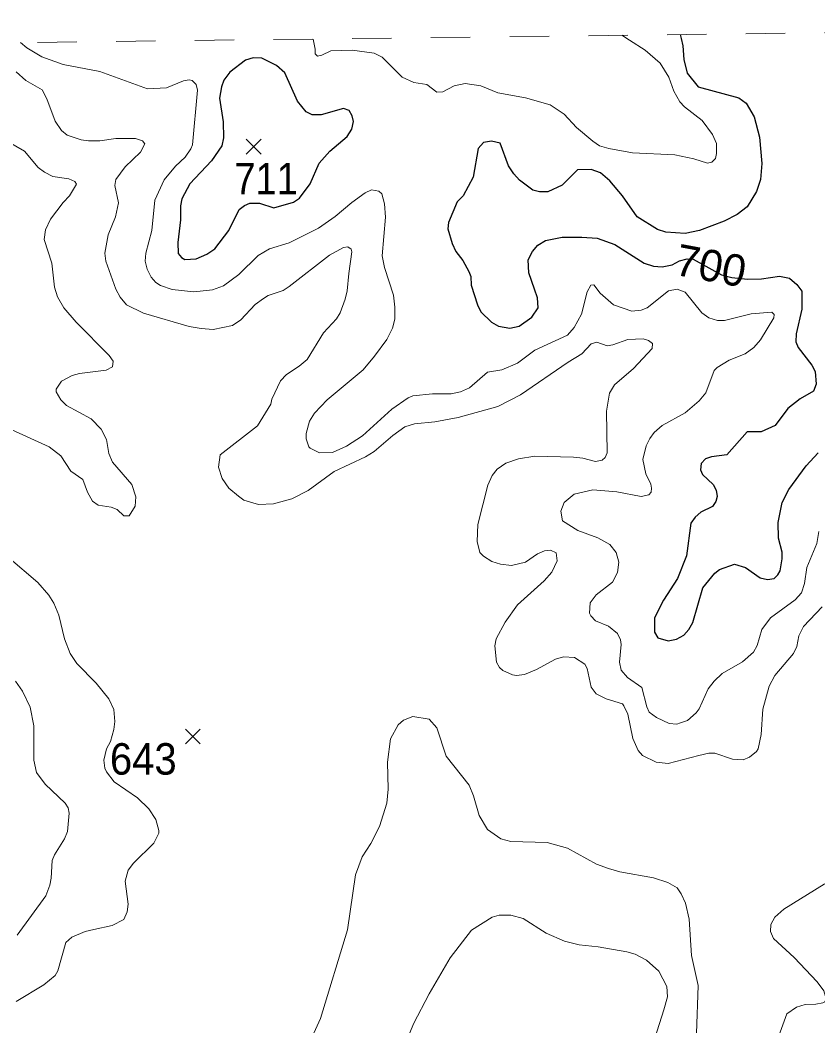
# Model space of a CAD drawing. Extents: x 294.2 to 320.3, y 7482.7 to 7510.7.
# Drawn here: x 315.257 to 317.284, y 7508.188 to 7510.744 of the extents above; entities that cross this region are included whole.
import ezdxf
from ezdxf.enums import TextEntityAlignment as Align

# ---------------------------------------------------------------- set-up
doc = ezdxf.new("R2010")
doc.units = 0
doc.header["$LTSCALE"] = 0.032
doc.linetypes.add('SHORT_DASHED', pattern=[2.7, 1.5, -1.2])
for name, color, linetype, lineweight in [('1', 7, 'Continuous', 25), ('2', 7, 'Continuous', 13), ('21', 7, 'Continuous', 25), ('22', 7, 'SHORT_DASHED', 13)]:
    doc.layers.add(name, color=color, linetype=linetype, lineweight=lineweight)
doc.layers.add('61', color=7, linetype='Continuous')

msp = doc.modelspace()

# ---------------------------------------------------------------- linework, layer by layer
at = {"layer": '1'}
for points in [[(316.9344, 7510.7069), (316.9364, 7510.6967), (316.941, 7510.6787), (316.9438, 7510.6432), (316.9521, 7510.6088), (316.9798, 7510.5744), (317.0835, 7510.5459), (317.1018, 7510.5324), (317.1223, 7510.498), (317.1361, 7510.4464), (317.1417, 7510.3792), (317.1384, 7510.3389), (317.1284, 7510.3082), (317.104, 7510.2689), (317.079, 7510.2501), (317.0463, 7510.2329), (316.983, 7510.2087), (316.947, 7510.2012), (316.8977, 7510.205), (316.8766, 7510.2115), (316.8245, 7510.2442), (316.7873, 7510.2969), (316.7552, 7510.3351), (316.7319, 7510.3556), (316.708, 7510.3642), (316.6731, 7510.3636), (316.6343, 7510.3244), (316.5977, 7510.3077), (316.5766, 7510.3071), (316.56, 7510.312), (316.5256, 7510.3367), (316.5117, 7510.3528), (316.4984, 7510.3738), (316.4767, 7510.4314), (316.4551, 7510.4362), (316.4346, 7510.4325), (316.4213, 7510.4174), (316.4085, 7510.3443), (316.383, 7510.2975), (316.3675, 7510.2819), (316.3453, 7510.2297), (316.3442, 7510.213), (316.3547, 7510.1759), (316.3642, 7510.156), (316.3824, 7510.1328), (316.3974, 7510.1049), (316.4024, 7510.092), (316.4035, 7510.0705), (316.4191, 7510.0199), (316.4279, 7510.0027), (316.4551, 7509.9763), (316.4723, 7509.9661), (316.5011, 7509.9613), (316.5255, 7509.9656), (316.5572, 7509.9892), (316.5735, 7510.0129), (316.572, 7510.0378), (316.5641, 7510.0603), (316.5497, 7510.1017), (316.548, 7510.1345), (316.5586, 7510.156), (316.5725, 7510.1716), (316.5924, 7510.1834), (316.634, 7510.192), (316.6845, 7510.1925), (316.7234, 7510.1898), (316.7683, 7510.1732), (316.8424, 7510.1264), (316.8668, 7510.1183), (316.8884, 7510.1167), (316.9134, 7510.1221), (316.9328, 7510.1323), (316.9522, 7510.1371), (316.9672, 7510.1366), (317.0388, 7510.0963), (317.0654, 7510.0898), (317.1053, 7510.0855), (317.1408, 7510.0865), (317.1868, 7510.093), (317.2118, 7510.0876), (317.2306, 7510.072), (317.2434, 7510.0548), (317.2429, 7510.0091), (317.2285, 7509.9462), (317.2279, 7509.9258), (317.2335, 7509.9118), (317.2689, 7509.8672), (317.2767, 7509.8511), (317.28, 7509.8188), (317.2728, 7509.8005), (317.239, 7509.7812), (317.2074, 7509.7565), (317.1752, 7509.714), (317.1397, 7509.6979), (317.1042, 7509.6974)], [(317.1042, 7509.6974), (317.0526, 7509.6393), (317.0138, 7509.6339), (316.9983, 7509.6285), (316.9877, 7509.6167), (316.9861, 7509.6005), (316.9911, 7509.5887)], [(316.9911, 7509.5887), (317.0177, 7509.5634), (317.026, 7509.5489), (317.0282, 7509.5328), (317.0249, 7509.5204), (317.0165, 7509.508), (316.9866, 7509.493), (316.9722, 7509.4806), (316.9616, 7509.4655), (316.95, 7509.3827), (316.9272, 7509.3252), (316.8917, 7509.2698), (316.869, 7509.2246), (316.869, 7509.1881), (316.8773, 7509.1741), (316.9039, 7509.166), (316.9244, 7509.1703), (316.9433, 7509.1805), (316.956, 7509.195), (316.966, 7509.2128), (316.9915, 7509.301), (317.022, 7509.3386), (317.0342, 7509.3478), (317.0719, 7509.3612), (317.1002, 7509.3526), (317.1374, 7509.3267), (317.1562, 7509.3219), (317.1729, 7509.3251), (317.1823, 7509.3337), (317.1879, 7509.3445), (317.1934, 7509.3746), (317.1929, 7509.3913), (317.184, 7509.4273), (317.1829, 7509.4671), (317.1929, 7509.5177), (317.2106, 7509.551), (317.2544, 7509.6112), (317.2849, 7509.644)]]:
    msp.add_lwpolyline(points, dxfattribs=at)
msp.add_lwpolyline([(315.7435, 7510.3859), (315.6886, 7510.3275), (315.6682, 7510.2899), (315.6643, 7510.272), (315.6643, 7510.2362), (315.6579, 7510.1788), (315.6588, 7510.1509), (315.6671, 7510.1403), (315.6761, 7510.1358), (315.7048, 7510.1373), (315.732, 7510.1493), (315.7517, 7510.1629), (315.7872, 7510.209), (315.8137, 7510.2626), (315.8273, 7510.2724), (315.8409, 7510.2785), (315.8651, 7510.2785), (315.9021, 7510.2664), (315.9516, 7510.2808), (315.9667, 7510.2913), (315.9939, 7510.3276), (316.0168, 7510.3799), (316.0442, 7510.4105), (316.0881, 7510.4483), (316.1002, 7510.4664), (316.104, 7510.486), (316.101, 7510.5004), (316.0934, 7510.514), (316.0791, 7510.5193), (316.0224, 7510.5034), (315.999, 7510.5026), (315.9839, 7510.511), (315.962, 7510.5381), (315.9299, 7510.6098), (315.9088, 7510.628), (315.8711, 7510.6469), (315.8492, 7510.6476), (315.8296, 7510.6416), (315.7903, 7510.6114), (315.7749, 7510.591), (315.7686, 7510.5745), (315.7642, 7510.545), (315.7732, 7510.4854), (315.774, 7510.4446), (315.7699, 7510.4242)], close=True, dxfattribs=at)
at = {"layer": '2'}
for points in [[(315.2582, 7510.6867), (315.274, 7510.6735), (315.3126, 7510.6506), (315.3662, 7510.6308), (315.4594, 7510.6129), (315.5807, 7510.5695), (315.6293, 7510.572), (315.672, 7510.5893), (315.6867, 7510.5919), (315.6944, 7510.5906), (315.7046, 7510.5804), (315.7078, 7510.5657), (315.695, 7510.4265), (315.6912, 7510.4163), (315.6765, 7510.3958), (315.6516, 7510.3722), (315.6229, 7510.3377), (315.5998, 7510.286), (315.5922, 7510.2094), (315.5763, 7510.1519), (315.575, 7510.1315), (315.5801, 7510.1111), (315.5903, 7510.0907), (315.6018, 7510.0772), (315.6139, 7510.0696), (315.6433, 7510.0594), (315.6982, 7510.053), (315.746, 7510.0583), (315.7742, 7510.0689), (315.8125, 7510.0976), (315.8617, 7510.1455), (315.891, 7510.1628), (315.9408, 7510.1781), (316.0155, 7510.2152), (316.0577, 7510.2445), (316.1004, 7510.2803), (316.1337, 7510.3052), (316.1503, 7510.3128), (316.1688, 7510.309), (316.1758, 7510.302), (316.1828, 7510.2771), (316.1854, 7510.2426), (316.177, 7510.1449), (316.1828, 7510.1149), (316.2058, 7510.0447), (316.2096, 7510.014), (316.209, 7509.9834), (316.2032, 7509.961), (316.1892, 7509.9323), (316.1579, 7509.8895), (316.1285, 7509.855), (316.0372, 7509.7791), (316.0053, 7509.7446), (315.9925, 7509.7242), (315.9842, 7509.6935), (315.9836, 7509.6801), (315.9906, 7509.659), (315.9944, 7509.6558), (316.0175, 7509.6444), (316.0506, 7509.645), (316.0864, 7509.6609), (316.1273, 7509.6877), (316.2013, 7509.7548), (316.2435, 7509.7842), (316.255, 7509.7886), (316.3048, 7509.7944), (316.352, 7509.7938), (316.3763, 7509.7989), (316.3986, 7509.8097), (316.4446, 7509.8487), (316.481, 7509.8551), (316.5206, 7509.8717), (316.5652, 7509.9049), (316.6476, 7509.9432), (316.6648, 7509.963), (316.6834, 7509.9962), (316.698, 7510.0536), (316.707, 7510.0702), (316.7146, 7510.0709), (316.7306, 7510.0498), (316.7648, 7510.0202), (316.8117, 7510.0045), (316.8347, 7510.007), (316.85, 7510.0127), (316.9049, 7510.0555), (316.9266, 7510.06), (316.9471, 7510.0523), (316.9892, 7510), (317.0071, 7509.9872), (317.0288, 7509.9808), (317.0467, 7509.9808), (317.1144, 7509.9974), (317.1667, 7510.0019), (317.1731, 7509.9958), (317.1725, 7509.9874)], [(316.0019, 7510.6957), (316.0066, 7510.6703), (316.0068, 7510.6578), (316.0127, 7510.6519), (316.0236, 7510.6544), (316.0468, 7510.6659), (316.1005, 7510.6672), (316.1566, 7510.6595), (316.1771, 7510.6493), (316.2282, 7510.5989), (316.2575, 7510.5855), (316.2907, 7510.5797), (316.3162, 7510.5605), (316.3315, 7510.5612), (316.3597, 7510.5765), (316.3878, 7510.5829), (316.4273, 7510.5771), (316.4708, 7510.5593), (316.541, 7510.5465), (316.6042, 7510.528), (316.6393, 7510.505), (316.6706, 7510.4712), (316.7121, 7510.4361), (316.7293, 7510.4239), (316.753, 7510.4175), (316.813, 7510.4067), (316.9203, 7510.4016), (316.9688, 7510.3914), (317.0033, 7510.3805), (317.0148, 7510.383), (317.0236, 7510.392), (317.0262, 7510.4048), (317.0262, 7510.4303), (317.016, 7510.4533), (316.9898, 7510.4884), (316.9451, 7510.5235), (316.9337, 7510.5363), (316.9183, 7510.5631), (316.9056, 7510.5989), (316.8832, 7510.6346), (316.8449, 7510.6672), (316.8053, 7510.6927), (316.7863, 7510.7052)], [(315.2468, 7510.6123), (315.2717, 7510.5899), (315.3132, 7510.5663), (315.3247, 7510.544), (315.3464, 7510.4865), (315.3623, 7510.4635), (315.377, 7510.4514), (315.4122, 7510.4392), (315.4313, 7510.4367), (315.4594, 7510.4367), (315.5003, 7510.443), (315.5501, 7510.443), (315.568, 7510.4367), (315.5743, 7510.4297), (315.5628, 7510.408), (315.5239, 7510.3709), (315.5002, 7510.339), (315.4977, 7510.3231), (315.5073, 7510.2796), (315.4996, 7510.2439), (315.4811, 7510.1979), (315.4728, 7510.1519), (315.4747, 7510.1315), (315.5002, 7510.06), (315.5118, 7510.0396), (315.5277, 7510.0204), (315.5705, 7509.9993), (315.6867, 7509.9649), (315.7174, 7509.9598), (315.748, 7509.9572), (315.7965, 7509.9674), (315.8176, 7509.9821), (315.854, 7510.0211), (315.8757, 7510.0364), (315.8872, 7510.044), (315.9255, 7510.0568), (315.9408, 7510.0664), (316.0436, 7510.1468), (316.0787, 7510.1659), (316.0896, 7510.1679), (316.0979, 7510.1615), (316.0998, 7510.1545), (316.0921, 7510.0996), (316.0883, 7510.0562), (316.0832, 7510.0345), (316.0704, 7510), (316.0608, 7509.9847), (316.0283, 7509.9489), (315.9862, 7509.8812), (315.9664, 7509.864), (315.9338, 7509.8429), (315.9191, 7509.8269), (315.8968, 7509.7804), (315.8942, 7509.7676), (315.8604, 7509.7126), (315.7652, 7509.6392), (315.7614, 7509.608), (315.7704, 7509.5786), (315.7876, 7509.5543), (315.8118, 7509.5339), (315.8259, 7509.5236), (315.8629, 7509.5128), (315.9006, 7509.5147), (315.9472, 7509.5269), (315.9887, 7509.5486), (316.0551, 7509.5964), (316.1349, 7509.6341), (316.1566, 7509.6475), (316.2039, 7509.6884), (316.2345, 7509.7101), (316.2588, 7509.7177), (316.3112, 7509.7228), (316.3699, 7509.7337), (316.4708, 7509.7618), (316.5282, 7509.7918), (316.6495, 7509.8748), (316.6846, 7509.8959), (316.7076, 7509.9214), (316.7223, 7509.9253), (316.7485, 7509.9163), (316.7632, 7509.9182), (316.8015, 7509.9323), (316.8398, 7509.9335), (316.8539, 7509.9297), (316.864, 7509.9221), (316.8634, 7509.9093), (316.8155, 7509.8583), (316.767, 7509.8167), (316.7542, 7509.7957), (316.7466, 7509.7497), (316.7485, 7509.6437), (316.7434, 7509.6322), (316.7363, 7509.6258)], [(315.2079, 7510.445), (315.2685, 7510.4111), (315.303, 7510.369), (315.3192, 7510.3571), (315.3402, 7510.3462), (315.3812, 7510.3404), (315.3961, 7510.3337), (315.4007, 7510.3271), (315.3828, 7510.2975), (315.3662, 7510.2802), (315.3343, 7510.2375), (315.3221, 7510.2107), (315.3183, 7510.1864), (315.3375, 7510.1264), (315.3445, 7510.0651), (315.3521, 7510.0409), (315.3687, 7510.0127), (315.3994, 7509.9764), (315.4837, 7509.8915), (315.4933, 7509.8774), (315.492, 7509.8627), (315.476, 7509.8538), (315.4083, 7509.8454), (315.3892, 7509.8403), (315.3623, 7509.8263), (315.349, 7509.8059), (315.349, 7509.7989), (315.3611, 7509.7784), (315.3751, 7509.7644), (315.4377, 7509.7305), (315.4632, 7509.7043), (315.4766, 7509.6782), (315.483, 7509.6424), (315.492, 7509.6207), (315.5411, 7509.5633), (315.5513, 7509.5326), (315.5494, 7509.5083), (315.5341, 7509.4841), (315.5207, 7509.4841), (315.5035, 7509.5), (315.4888, 7509.5064), (315.4556, 7509.5115), (315.4415, 7509.5217), (315.4281, 7509.5441), (315.4166, 7509.576), (315.386, 7509.5977), (315.3604, 7509.6361), (315.3311, 7509.6597), (315.2174, 7509.7107)], [(317.1725, 7509.9874), (317.138, 7509.931), (317.1214, 7509.9119), (317.099, 7509.8959), (317.0582, 7509.8793), (317.0281, 7509.8608), (317.0205, 7509.8531)], [(317.0205, 7509.8531), (316.9994, 7509.7963), (316.9828, 7509.7759), (316.9471, 7509.7458), (316.8883, 7509.7133), (316.8685, 7509.696), (316.857, 7509.6808), (316.8481, 7509.6616), (316.8392, 7509.6271), (316.8468, 7509.5907), (316.8596, 7509.5646), (316.8615, 7509.5543), (316.8602, 7509.5441), (316.8545, 7509.5371), (316.8347, 7509.5333), (316.7734, 7509.5454), (316.7121, 7509.5499), (316.6648, 7509.539), (316.6393, 7509.5179), (316.631, 7509.4956), (316.6355, 7509.4713), (316.6738, 7509.4464), (316.7249, 7509.4285), (316.7555, 7509.4113), (316.7715, 7509.3909), (316.7779, 7509.3666), (316.7746, 7509.3398), (316.7625, 7509.3155), (316.721, 7509.2829), (316.7051, 7509.2632), (316.7038, 7509.237), (316.707, 7509.23), (316.7191, 7509.2172), (316.7517, 7509.2038), (316.7746, 7509.1853), (316.7823, 7509.1693), (316.7843, 7509.1572), (316.7804, 7509.1125), (316.7843, 7509.0921), (316.8002, 7509.0736), (316.8366, 7509.0474), (316.8494, 7508.9989), (316.8557, 7508.9854), (316.8736, 7508.972), (316.9062, 7508.9561), (316.926, 7508.9548), (316.9349, 7508.958), (316.9528, 7508.9637), (316.9751, 7508.9835), (316.9828, 7508.9937), (317.0052, 7509.0448), (317.0205, 7509.064), (317.0409, 7509.0831), (317.0927, 7509.1131), (317.1207, 7509.1374), (317.1297, 7509.1546), (317.1418, 7509.1955), (317.1635, 7509.2249), (317.2267, 7509.2702), (317.242, 7509.2881), (317.2503, 7509.3117), (317.2561, 7509.3526), (317.2816, 7509.4139), (317.2867, 7509.4445)], [(316.4912, 7509.6182), (316.4695, 7509.6022), (316.4561, 7509.5869), (316.4452, 7509.562), (316.4203, 7509.4624), (316.418, 7509.4189), (316.4249, 7509.3911), (316.4341, 7509.3816), (316.4554, 7509.3682), (316.4778, 7509.361), (316.5053, 7509.3576), (316.541, 7509.3666), (316.5717, 7509.3877), (316.5895, 7509.3953), (316.6048, 7509.3972), (316.6195, 7509.3902), (316.6214, 7509.3698), (316.608, 7509.3411), (316.5882, 7509.3187), (316.5205, 7509.2581), (316.4893, 7509.214), (316.4669, 7509.1719), (316.4637, 7509.154), (316.4676, 7509.1125), (316.4752, 7509.0984), (316.4835, 7509.0908), (316.5078, 7509.0799), (316.518, 7509.078), (316.5385, 7509.0805), (316.5691, 7509.0933), (316.6176, 7509.1201), (316.6381, 7509.1259), (316.6655, 7509.124), (316.6923, 7509.1067), (316.698, 7509.0965), (316.7083, 7509.0487), (316.721, 7509.032), (316.746, 7509.0186), (316.7874, 7509.0065), (316.7913, 7509.0014), (316.8009, 7508.9797), (316.8136, 7508.9184), (316.8277, 7508.8878), (316.8385, 7508.875), (316.873, 7508.8577), (316.9037, 7508.8545), (316.9816, 7508.875), (317.0071, 7508.8813), (317.0218, 7508.8813), (317.0671, 7508.8654), (317.0939, 7508.8641), (317.1105, 7508.8705), (317.1278, 7508.8852), (317.1322, 7508.8922), (317.1399, 7508.9286), (317.1444, 7508.9925), (317.1603, 7509.0512), (317.175, 7509.078), (317.2223, 7509.1342), (317.2305, 7509.1521), (317.2356, 7509.1789), (317.2478, 7509.2032), (317.295, 7509.253)], [(316.7363, 7509.6258), (316.7187, 7509.6225), (316.6866, 7509.6309), (316.663, 7509.6331), (316.5653, 7509.6354), (316.5231, 7509.629), (316.4912, 7509.6182)], [(315.5206, 7508.4581), (315.5293, 7508.4776), (315.5315, 7508.4976), (315.5245, 7508.5558), (315.5316, 7508.5839), (315.5456, 7508.6017), (315.5967, 7508.6521), (315.6095, 7508.6777), (315.6095, 7508.6847), (315.6018, 7508.7128), (315.5839, 7508.7396), (315.5552, 7508.7671), (315.4964, 7508.8079), (315.4768, 7508.8333), (315.4722, 7508.8428), (315.4699, 7508.8634), (315.4763, 7508.8918), (315.4866, 7508.911), (315.4951, 7508.9414), (315.4977, 7508.9618), (315.4952, 7508.9918), (315.4824, 7509.0186), (315.4505, 7509.0589), (315.4013, 7509.1087), (315.3841, 7509.1342), (315.37, 7509.1712), (315.3559, 7509.2313), (315.3432, 7509.2619), (315.3304, 7509.2823), (315.3023, 7509.3143), (315.227, 7509.3787)], [(315.2499, 7508.4181), (315.3228, 7508.5187), (315.333, 7508.5455), (315.3362, 7508.5634), (315.3387, 7508.6081), (315.3445, 7508.6228), (315.37, 7508.663), (315.3777, 7508.6822), (315.3815, 7508.7281), (315.3789, 7508.7422), (315.3713, 7508.7537), (315.3209, 7508.8022), (315.2985, 7508.8322), (315.2921, 7508.8635), (315.2921, 7508.9503), (315.2825, 7508.9982), (315.2634, 7509.0384), (315.2455, 7509.064)], [(316.9758, 7508.1688), (316.9802, 7508.2908), (316.963, 7508.3668), (316.9566, 7508.4587), (316.9477, 7508.4996), (316.9368, 7508.5238), (316.9266, 7508.5385), (316.9024, 7508.5526), (316.8666, 7508.5641), (316.7811, 7508.5794), (316.7517, 7508.5876), (316.7217, 7508.5985), (316.6476, 7508.6394), (316.5959, 7508.654), (316.504, 7508.6566), (316.4783, 7508.6633), (316.445, 7508.6867), (316.4237, 7508.7229), (316.4094, 7508.7728), (316.398, 7508.7997), (316.3399, 7508.8737), (316.3162, 7508.9452), (316.2965, 7508.9675), (316.2549, 7508.974), (316.2313, 7508.9644), (316.2179, 7508.9528), (316.1981, 7508.9171), (316.1905, 7508.8584), (316.1924, 7508.7894), (316.1892, 7508.7537), (316.17, 7508.6949), (316.1483, 7508.6515), (316.1266, 7508.6171), (316.1094, 7508.5717), (316.0889, 7508.4319), (316.02, 7508.2071), (315.9951, 7508.1509)], [(317.4566, 7508.594), (317.3978, 7508.5883), (317.3544, 7508.5781), (317.3001, 7508.5481), (317.1973, 7508.4842), (317.175, 7508.4644), (317.1648, 7508.4459)], [(316.8589, 7508.1222), (316.8928, 7508.2289), (316.9023, 7508.2621), (316.9005, 7508.2876), (316.88, 7508.3272), (316.8487, 7508.3552), (316.82, 7508.3706), (316.7989, 7508.3763), (316.7262, 7508.3891), (316.6776, 7508.3942), (316.6406, 7508.4032), (316.594, 7508.4236), (316.5352, 7508.4612), (316.504, 7508.4696), (316.4746, 7508.4696), (316.4567, 7508.4644), (316.4037, 7508.4312), (316.3494, 7508.361), (316.2965, 7508.2697), (316.2569, 7508.1931), (316.1943, 7508.0386)], [(315.3534, 7508.3278), (315.3738, 7508.4), (315.3885, 7508.4134), (315.4224, 7508.4274), (315.4441, 7508.4325), (315.4914, 7508.4427), (315.5206, 7508.4581)], [(317.1648, 7508.4459), (317.1635, 7508.4281), (317.1712, 7508.4102), (317.2235, 7508.3616), (317.2822, 7508.3003), (317.2995, 7508.2767), (317.3053, 7508.257), (317.302, 7508.2492), (317.2969, 7508.2467), (317.2791, 7508.2429), (317.2516, 7508.2423), (317.2293, 7508.2359), (317.205, 7508.2186), (317.1846, 7508.1625)], [(315.2468, 7508.2499), (315.3177, 7508.2921), (315.3464, 7508.3163), (315.3534, 7508.3278)]]:
    msp.add_lwpolyline(points, dxfattribs=at)
at = {"layer": '21'}
for p, q in [((315.8318, 7510.4409), (315.8693, 7510.4034)), ((315.8693, 7510.4409), (315.8318, 7510.4034)), ((315.6771, 7508.942), (315.7146, 7508.9045)), ((315.7146, 7508.942), (315.6771, 7508.9045))]:
    msp.add_line(p, q, dxfattribs=at)
at = {"layer": '22'}
msp.add_lwpolyline([(294.2515, 7510.4214), (307.9016, 7510.5978), (319.9762, 7510.7437)], dxfattribs=at)

# ---------------------------------------------------------------- texts
at = {"layer": '61'}
for s, width, p in [('711', 0.9, (315.8822, 7510.3009)), ('643', 0.95, (315.5702, 7508.8264))]:
    msp.add_text(s, height=0.08, dxfattribs=dict(at, width=width)).set_placement(p, align=Align.CENTER)
msp.add_text('700', height=0.08, rotation=349.358, dxfattribs=at).set_placement((317.005, 7510.0806), align=Align.CENTER)

doc.saveas('drawing.dxf')
